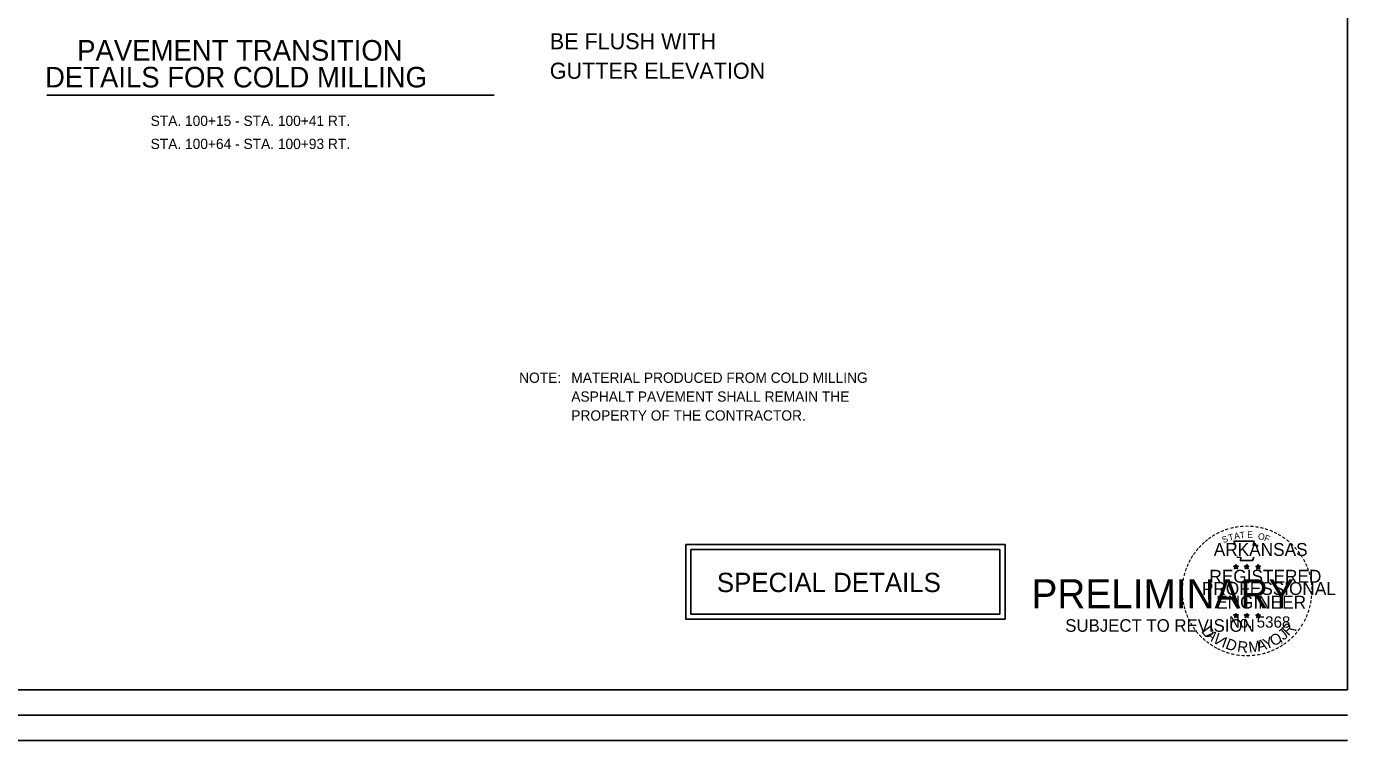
# Model space of a CAD drawing. Extents: x 1944905 to 1956777, y 763871 to 764977.
# Drawn here: x 1955751 to 1956777, y 763871 to 764425 of the extents above; entities that cross this region are included whole.
import ezdxf

# ---------------------------------------------------------------- set-up
doc = ezdxf.new("R2010")
doc.units = 0
for name, color, linetype in [('Default', 7, 'Continuous'), ('R_Border PE', 7, 'Continuous'), ('R_Dimension', 7, 'Continuous')]:
    doc.layers.add(name, color=color, linetype=linetype)

msp = doc.modelspace()

# ---------------------------------------------------------------- linework, layer by layer
at = {"layer": 'Default'}
for p, q in [((1956776.6, 763910.1), (1956776.6, 764937.3)), ((1956776.6, 763910.1), (1955195.7, 763910.1)), ((1955162.8, 763890.4), (1956776.6, 763890.4)), ((1955162.8, 763870.7), (1956776.6, 763870.7))]:
    msp.add_line(p, q, dxfattribs=at)
for points in [[(1956262.7, 764022.9), (1956510.7, 764022.9), (1956510.7, 763964.9), (1956262.7, 763964.9)], [(1956266.7, 764018.9), (1956506.7, 764018.9), (1956506.7, 763968.9), (1956266.7, 763968.9)]]:
    msp.add_lwpolyline(points, close=True, dxfattribs=at)
at = {"layer": 'R_Border PE'}
for p, q in [((1956688.2, 764006), (1956689.9, 764005.5)), ((1956688.2, 764006), (1956689.5, 764005.9)), ((1956688.2, 764006), (1956689.5, 764005.8)), ((1956688.2, 764006), (1956689.4, 764005.7)), ((1956688.2, 764006), (1956689.4, 764005.5)), ((1956688.2, 764006), (1956689.4, 764005.4)), ((1956688.2, 764006), (1956689.4, 764005.3)), ((1956689.9, 764007.3), (1956689.7, 764006)), ((1956689.9, 764007.3), (1956689.7, 764006.1)), ((1956689.9, 764005.5), (1956689.9, 764007.3)), ((1956689.9, 764007.3), (1956690.3, 764006)), ((1956689.9, 764007.3), (1956690.2, 764006)), ((1956689.9, 764007.3), (1956690.1, 764006.1)), ((1956689.9, 764007.3), (1956689.9, 764006)), ((1956691.7, 764006), (1956689.9, 764005.5)), ((1956691.7, 764006), (1956690.2, 764005.9)), ((1956691.7, 764006), (1956690.3, 764005.8)), ((1956691.7, 764006), (1956690.3, 764005.7)), ((1956691.7, 764006), (1956690.6, 764005.6)), ((1956691.7, 764006), (1956690.7, 764005.5)), ((1956691.7, 764006), (1956690.7, 764005.5)), ((1956696.5, 764006), (1956698.3, 764005.5)), ((1956696.5, 764006), (1956697.8, 764005.9)), ((1956696.5, 764006), (1956697.8, 764005.8)), ((1956696.5, 764006), (1956697.8, 764005.7)), ((1956696.5, 764006), (1956697.8, 764005.5)), ((1956696.5, 764006), (1956697.7, 764005.4)), ((1956696.5, 764006), (1956697.7, 764005.3)), ((1956698.3, 764007.3), (1956698, 764006.1)), ((1956698.3, 764007.3), (1956698.1, 764006)), ((1956698.3, 764007.3), (1956698.2, 764006)), ((1956698.3, 764005.5), (1956698.3, 764007.3)), ((1956698.3, 764007.3), (1956698.6, 764006)), ((1956698.3, 764007.3), (1956698.5, 764006)), ((1956698.3, 764007.3), (1956698.4, 764006.1)), ((1956700, 764006), (1956698.3, 764005.5)), ((1956700, 764006), (1956698.5, 764005.9)), ((1956700, 764006), (1956698.6, 764005.8)), ((1956700, 764006), (1956698.6, 764005.7)), ((1956700, 764006), (1956698.9, 764005.6)), ((1956700, 764006), (1956699, 764005.5)), ((1956700, 764006), (1956699.1, 764005.5)), ((1956705.4, 764006), (1956707.1, 764005.4)), ((1956705.4, 764006), (1956706.7, 764005.8)), ((1956705.4, 764006), (1956706.7, 764005.7)), ((1956705.4, 764006), (1956706.6, 764005.6)), ((1956705.4, 764006), (1956706.6, 764005.5)), ((1956705.4, 764006), (1956706.6, 764005.4)), ((1956705.4, 764006), (1956706.6, 764005.3)), ((1956707.1, 764007.2), (1956706.8, 764006)), ((1956707.1, 764007.2), (1956706.9, 764006)), ((1956707.1, 764007.2), (1956707, 764006)), ((1956707.1, 764005.4), (1956707.1, 764007.2)), ((1956707.1, 764007.2), (1956707.5, 764006)), ((1956707.1, 764007.2), (1956707.4, 764006)), ((1956707.1, 764007.2), (1956707.2, 764006)), ((1956708.9, 764006), (1956707.1, 764005.4)), ((1956708.9, 764006), (1956707.3, 764005.9)), ((1956708.9, 764006), (1956707.4, 764005.7)), ((1956708.9, 764006), (1956707.4, 764005.6)), ((1956708.9, 764006), (1956707.8, 764005.5)), ((1956708.9, 764006), (1956707.8, 764005.5)), ((1956708.9, 764006), (1956707.9, 764005.4)), ((1956688.9, 764004), (1956689.9, 764005.5)), ((1956688.9, 764004), (1956689.4, 764005.4)), ((1956688.9, 764004), (1956689.5, 764005.2)), ((1956688.9, 764004), (1956689.6, 764005.2)), ((1956688.9, 764004), (1956689.9, 764005.1)), ((1956688.9, 764004), (1956689.7, 764005)), ((1956688.9, 764004), (1956690, 764004.9)), ((1956691, 764004), (1956689.9, 764005.5)), ((1956691, 764004), (1956689.9, 764005.1)), ((1956691, 764004), (1956689.9, 764004.9)), ((1956691, 764004), (1956690.1, 764005)), ((1956691, 764004), (1956690.3, 764005.4)), ((1956691, 764004), (1956690.3, 764005.2)), ((1956691, 764004), (1956690.4, 764005.4)), ((1956697.2, 764004), (1956698.3, 764005.5)), ((1956697.2, 764004), (1956697.8, 764005.4)), ((1956697.2, 764004), (1956697.8, 764005.2)), ((1956697.2, 764004), (1956697.9, 764005.2)), ((1956697.2, 764004), (1956698.3, 764005.1)), ((1956697.2, 764004), (1956698.1, 764005)), ((1956697.2, 764004), (1956698.3, 764004.9)), ((1956699.4, 764004), (1956698.3, 764005.5)), ((1956699.4, 764004), (1956698.3, 764005.1)), ((1956699.4, 764004), (1956698.3, 764004.9)), ((1956699.4, 764004), (1956698.5, 764005)), ((1956699.4, 764004), (1956698.6, 764005.2)), ((1956699.4, 764004), (1956698.7, 764005.4)), ((1956699.4, 764004), (1956698.8, 764005.4)), ((1956706.1, 764003.9), (1956707.1, 764005.4)), ((1956706.1, 764003.9), (1956706.6, 764005.3)), ((1956706.1, 764003.9), (1956706.7, 764005.1)), ((1956706.1, 764003.9), (1956706.8, 764005.1)), ((1956706.1, 764003.9), (1956706.9, 764005)), ((1956706.1, 764003.9), (1956707.1, 764005)), ((1956706.1, 764003.9), (1956707.2, 764004.9)), ((1956708.2, 764003.9), (1956707.1, 764005.4)), ((1956708.2, 764003.9), (1956707.1, 764005)), ((1956708.2, 764003.9), (1956707.1, 764004.9)), ((1956708.2, 764003.9), (1956707.3, 764005)), ((1956708.2, 764003.9), (1956707.5, 764005.4)), ((1956708.2, 764003.9), (1956707.5, 764005.2)), ((1956708.2, 764003.9), (1956707.6, 764005.4)), ((1956688.2, 763968.2), (1956689.9, 763967.6)), ((1956688.2, 763968.2), (1956689.5, 763968)), ((1956688.2, 763968.2), (1956689.5, 763967.9)), ((1956688.2, 763968.2), (1956689.4, 763967.8)), ((1956688.2, 763968.2), (1956689.4, 763967.7)), ((1956688.2, 763968.2), (1956689.4, 763967.6)), ((1956688.2, 763968.2), (1956689.4, 763967.4)), ((1956688.9, 763966.1), (1956689.9, 763967.6)), ((1956688.9, 763966.1), (1956689.4, 763967.5)), ((1956688.9, 763966.1), (1956689.5, 763967.3)), ((1956688.9, 763966.1), (1956689.6, 763967.3)), ((1956688.9, 763966.1), (1956689.7, 763967.2)), ((1956688.9, 763966.1), (1956689.9, 763967.2)), ((1956688.9, 763966.1), (1956690, 763967.1)), ((1956689.9, 763969.4), (1956689.6, 763968.2)), ((1956689.9, 763969.4), (1956689.7, 763968.2)), ((1956689.9, 763969.4), (1956689.8, 763968.2)), ((1956689.9, 763967.6), (1956689.9, 763969.4)), ((1956689.9, 763969.4), (1956690.3, 763968.2)), ((1956689.9, 763969.4), (1956690.2, 763968.2)), ((1956689.9, 763969.4), (1956690, 763968.2)), ((1956691.7, 763968.2), (1956689.9, 763967.6)), ((1956691, 763966.1), (1956689.9, 763967.6)), ((1956691, 763966.1), (1956689.9, 763967.2)), ((1956691, 763966.1), (1956689.9, 763967.1)), ((1956691.7, 763968.2), (1956690.1, 763968.1)), ((1956691, 763966.1), (1956690.1, 763967.2)), ((1956691.7, 763968.2), (1956690.2, 763967.9)), ((1956691.7, 763968.2), (1956690.2, 763967.8)), ((1956691, 763966.1), (1956690.3, 763967.6)), ((1956691, 763966.1), (1956690.3, 763967.3)), ((1956691, 763966.1), (1956690.4, 763967.6)), ((1956691.7, 763968.2), (1956690.6, 763967.7)), ((1956691.7, 763968.2), (1956690.6, 763967.7)), ((1956691.7, 763968.2), (1956690.7, 763967.6)), ((1956696.5, 763968.2), (1956698.3, 763967.6)), ((1956696.5, 763968.2), (1956697.8, 763968)), ((1956696.5, 763968.2), (1956697.8, 763967.9)), ((1956696.5, 763968.2), (1956697.8, 763967.8)), ((1956696.5, 763968.2), (1956697.7, 763967.7)), ((1956696.5, 763968.2), (1956697.7, 763967.6)), ((1956696.5, 763968.2), (1956697.7, 763967.4)), ((1956697.2, 763966.1), (1956698.3, 763967.6)), ((1956697.2, 763966.1), (1956697.8, 763967.5)), ((1956697.2, 763966.1), (1956697.8, 763967.3)), ((1956697.2, 763966.1), (1956697.9, 763967.3)), ((1956697.2, 763966.1), (1956698.1, 763967.2)), ((1956697.2, 763966.1), (1956698.3, 763967.2)), ((1956697.2, 763966.1), (1956698.3, 763967.1)), ((1956698.3, 763969.4), (1956698, 763968.2)), ((1956698.3, 763969.4), (1956698.1, 763968.2)), ((1956698.3, 763969.4), (1956698.2, 763968.2)), ((1956698.3, 763967.6), (1956698.3, 763969.4)), ((1956698.3, 763969.4), (1956698.6, 763968.2)), ((1956698.3, 763969.4), (1956698.5, 763968.2)), ((1956698.3, 763969.4), (1956698.4, 763968.2)), ((1956700, 763968.2), (1956698.3, 763967.6)), ((1956699.3, 763966.1), (1956698.3, 763967.6)), ((1956699.3, 763966.1), (1956698.3, 763967.2)), ((1956699.3, 763966.1), (1956698.3, 763967.1)), ((1956700, 763968.2), (1956698.5, 763968.1)), ((1956699.3, 763966.1), (1956698.5, 763967.2)), ((1956700, 763968.2), (1956698.6, 763967.9)), ((1956700, 763968.2), (1956698.6, 763967.8)), ((1956699.3, 763966.1), (1956698.6, 763967.3)), ((1956699.3, 763966.1), (1956698.7, 763967.6)), ((1956699.3, 763966.1), (1956698.8, 763967.6)), ((1956700, 763968.2), (1956698.9, 763967.7)), ((1956700, 763968.2), (1956699, 763967.7)), ((1956700, 763968.2), (1956699.1, 763967.6)), ((1956705.4, 763968.1), (1956707.1, 763967.5)), ((1956705.4, 763968.1), (1956706.6, 763968)), ((1956705.4, 763968.1), (1956706.6, 763967.9)), ((1956705.4, 763968.1), (1956706.6, 763967.8)), ((1956705.4, 763968.1), (1956706.6, 763967.6)), ((1956705.4, 763968.1), (1956706.5, 763967.5)), ((1956705.4, 763968.1), (1956706.5, 763967.4)), ((1956706, 763966.1), (1956707.1, 763967.5)), ((1956706, 763966.1), (1956706.6, 763967.4)), ((1956706, 763966.1), (1956706.7, 763967.3)), ((1956706, 763966.1), (1956706.8, 763967.2)), ((1956706, 763966.1), (1956706.9, 763967.1)), ((1956706, 763966.1), (1956707.1, 763967.1)), ((1956706, 763966.1), (1956707.1, 763967)), ((1956707.1, 763969.4), (1956706.8, 763968.1)), ((1956707.1, 763969.4), (1956706.9, 763968.1)), ((1956707.1, 763969.4), (1956707, 763968.1)), ((1956707.1, 763967.5), (1956707.1, 763969.4)), ((1956707.1, 763969.4), (1956707.4, 763968.1)), ((1956707.1, 763969.4), (1956707.4, 763968.1)), ((1956707.1, 763969.4), (1956707.2, 763968.1)), ((1956708.8, 763968.1), (1956707.1, 763967.5)), ((1956708.2, 763966.1), (1956707.1, 763967.5)), ((1956708.2, 763966.1), (1956707.1, 763967.1)), ((1956708.2, 763966.1), (1956707.1, 763967)), ((1956708.8, 763968.1), (1956707.3, 763968)), ((1956708.2, 763966.1), (1956707.3, 763967.1)), ((1956708.8, 763968.1), (1956707.4, 763967.9)), ((1956708.8, 763968.1), (1956707.4, 763967.8)), ((1956708.2, 763966.1), (1956707.5, 763967.5)), ((1956708.2, 763966.1), (1956707.5, 763967.3)), ((1956708.2, 763966.1), (1956707.6, 763967.5)), ((1956708.8, 763968.1), (1956707.7, 763967.6)), ((1956708.8, 763968.1), (1956707.8, 763967.6)), ((1956708.8, 763968.1), (1956707.9, 763967.5))]:
    msp.add_line(p, q, dxfattribs=at)
for points in [[(1956688.4, 764025.4), (1956689.8, 764021.3)], [(1956706, 764020.8), (1956706.7, 764022.2), (1956703.2, 764022.1), (1956704, 764025.4), (1956688.4, 764025.4)], [(1956689.9, 764007.3), (1956691, 764004), (1956688.2, 764006), (1956691.7, 764006), (1956688.9, 764004), (1956689.9, 764007.3)], [(1956690.9, 764013.3), (1956690.9, 764012.9), (1956693.7, 764012.8), (1956693.4, 764010.4), (1956702.8, 764010.4), (1956703.8, 764013.1)], [(1956698.3, 764007.3), (1956699.4, 764004), (1956696.5, 764006), (1956700, 764006), (1956697.2, 764004), (1956698.3, 764007.3)], [(1956707.1, 764007.2), (1956708.2, 764003.9), (1956705.4, 764006), (1956708.9, 764006), (1956706.1, 764003.9), (1956707.1, 764007.2)], [(1956689.9, 763969.4), (1956691, 763966.1), (1956688.2, 763968.2), (1956691.7, 763968.2), (1956688.9, 763966.1), (1956689.9, 763969.4)], [(1956698.3, 763969.4), (1956699.3, 763966.1), (1956696.5, 763968.2), (1956700, 763968.2), (1956697.2, 763966.1), (1956698.3, 763969.4)], [(1956707.1, 763969.4), (1956708.2, 763966.1), (1956705.4, 763968.1), (1956708.8, 763968.1), (1956706, 763966.1), (1956707.1, 763969.4)]]:
    msp.add_lwpolyline(points, dxfattribs=at)
for centre, radius in [((1956689.9, 764005.5), 0.861), ((1956689.9, 764005.5), 0.78), ((1956689.9, 764005.5), 0.723), ((1956689.9, 764005.5), 0.664), ((1956689.9, 764005.5), 0.579), ((1956689.9, 764005.5), 0.537), ((1956698.3, 764005.5), 0.861), ((1956698.3, 764005.5), 0.78), ((1956698.3, 764005.5), 0.723), ((1956698.3, 764005.5), 0.664), ((1956698.3, 764005.5), 0.579), ((1956698.3, 764005.5), 0.537), ((1956707.1, 764005.4), 0.861), ((1956707.1, 764005.4), 0.78), ((1956707.1, 764005.4), 0.723), ((1956707.1, 764005.4), 0.664), ((1956707.1, 764005.4), 0.579), ((1956689.9, 764005.5), 0.495), ((1956689.9, 764005.5), 0.426), ((1956689.9, 764005.5), 0.374), ((1956689.9, 764005.5), 0.311), ((1956689.9, 764005.5), 0.248), ((1956689.9, 764005.5), 0.185), ((1956689.9, 764005.5), 0.148), ((1956689.9, 764005.5), 0.0721), ((1956698.3, 764005.5), 0.495), ((1956698.3, 764005.5), 0.426), ((1956698.3, 764005.5), 0.374), ((1956698.3, 764005.5), 0.311), ((1956698.3, 764005.5), 0.248), ((1956698.3, 764005.5), 0.185), ((1956698.3, 764005.5), 0.148), ((1956698.3, 764005.5), 0.0721), ((1956707.1, 764005.4), 0.537), ((1956707.1, 764005.4), 0.495), ((1956707.1, 764005.4), 0.426), ((1956707.1, 764005.4), 0.374), ((1956707.1, 764005.4), 0.311), ((1956707.1, 764005.4), 0.248), ((1956707.1, 764005.4), 0.185), ((1956707.1, 764005.4), 0.148), ((1956707.1, 764005.4), 0.0721), ((1956689.9, 763967.6), 0.861), ((1956689.9, 763967.6), 0.78), ((1956689.9, 763967.6), 0.723), ((1956689.9, 763967.6), 0.664), ((1956689.9, 763967.6), 0.579), ((1956689.9, 763967.6), 0.537), ((1956689.9, 763967.6), 0.495), ((1956689.9, 763967.6), 0.426), ((1956689.9, 763967.6), 0.374), ((1956689.9, 763967.6), 0.311), ((1956689.9, 763967.6), 0.248), ((1956689.9, 763967.6), 0.185), ((1956689.9, 763967.6), 0.148), ((1956689.9, 763967.6), 0.0721), ((1956698.3, 763967.6), 0.861), ((1956698.3, 763967.6), 0.78), ((1956698.3, 763967.6), 0.723), ((1956698.3, 763967.6), 0.664), ((1956698.3, 763967.6), 0.579), ((1956698.3, 763967.6), 0.537), ((1956698.3, 763967.6), 0.495), ((1956698.3, 763967.6), 0.426), ((1956698.3, 763967.6), 0.374), ((1956698.3, 763967.6), 0.311), ((1956698.3, 763967.6), 0.248), ((1956698.3, 763967.6), 0.185), ((1956698.3, 763967.6), 0.148), ((1956698.3, 763967.6), 0.0721), ((1956707.1, 763967.6), 0.861), ((1956707.1, 763967.6), 0.78), ((1956707.1, 763967.6), 0.723), ((1956707.1, 763967.6), 0.664), ((1956707.1, 763967.6), 0.579), ((1956707.1, 763967.6), 0.495), ((1956707.1, 763967.6), 0.537), ((1956707.1, 763967.6), 0.426), ((1956707.1, 763967.6), 0.374), ((1956707.1, 763967.6), 0.311), ((1956707.1, 763967.6), 0.248), ((1956707.1, 763967.6), 0.185), ((1956707.1, 763967.6), 0.148), ((1956707.1, 763967.6), 0.0721)]:
    msp.add_circle(centre, radius, dxfattribs=at)
at = {"layer": 'R_Dimension'}
msp.add_line((1955766.8, 764371.7), (1956113.9, 764371.7), dxfattribs=at)

# ---------------------------------------------------------------- texts
at = {"layer": 'Default'}
for s, height, p in [('SPECIAL DETAILS', 15, (1956286.9, 763985.9)), ('PRELIMINARY', 22.5, (1956531.2, 763973.4)), ('        SUBJECT TO REVISION', 9.75, (1956528.4, 763955.1))]:
    msp.add_text(s, height=height, dxfattribs=at).set_placement(p)
at = {"layer": 'R_Border PE'}
for s, height, rotation, p in [('-', 8, 10.2193, (1956689.3, 764033.1)), ('-', 8, 5.8968, (1956692.9, 764033.6)), ('-', 8, 0.1862, (1956696.8, 764034)), ('-', 8, 357.743, (1956700.4, 764033.9)), ('-', 8, 352.1617, (1956704.1, 764033.6)), ('-', 8, 38.9507, (1956667.6, 764022.4)), ('-', 8, 36.2317, (1956669.9, 764024.3)), ('-', 8, 34.0636, (1956672.8, 764026.3)), ('-', 8, 28.7918, (1956675.8, 764028.1)), ('-', 8, 24.3072, (1956679, 764029.7)), ('S', 5, 21.594, (1956680.2, 764023.8)), ('-', 8, 19.1761, (1956682.1, 764031.1)), ('T', 5, 16.4036, (1956684.8, 764025.5)), ('-', 8, 13.6301, (1956685.9, 764032.3)), ('A', 5, 11.2132, (1956688.9, 764026.7)), ('T', 5, 6.0228, (1956693.1, 764027.5)), ('E', 5, 0.8323, (1956698.7, 764028.1)), ('O', 5, 350.4515, (1956706.7, 764027)), ('-', 8, 347.2049, (1956707.7, 764033.1)), ('F', 5, 340.0707, (1956711.4, 764025.9)), ('-', 8, 342.3362, (1956710.9, 764032.3)), ('-', 8, 337.8551, (1956714.6, 764031.2)), ('-', 8, 334.1211, (1956717.7, 764029.8)), ('-', 8, 329.6409, (1956720.6, 764028.4)), ('-', 8, 325.8627, (1956723.8, 764026.6)), ('-', 8, 320.5297, (1956726.9, 764024.5)), ('-', 8, 54.2325, (1956659.1, 764012.7)), ('-', 8, 50.6142, (1956661.1, 764015.5)), ('-', 8, 48.4231, (1956663.2, 764017.9)), ('-', 8, 42.9622, (1956665.4, 764020.3)), ('-', 8, 315.5786, (1956729.9, 764022)), ('-', 8, 309.8797, (1956732.7, 764019.3)), ('-', 8, 306.6522, (1956735.4, 764016.3)), ('-', 8, 67.7743, (1956654.6, 764003.9)), ('-', 8, 62.8713, (1956655.9, 764007)), ('-', 8, 58.0706, (1956657.4, 764010)), ('-', 7, 303.6753, (1956737.8, 764013.4)), ('-', 8, 299.6684, (1956739.4, 764010.4)), ('-', 8, 294.6628, (1956741, 764007.3)), ('-', 8, 81.2013, (1956651.8, 763993.6)), ('-', 8, 75.461, (1956652.5, 763997.2)), ('-', 8, 72.3945, (1956653.5, 764000.8)), ('-', 8, 290.5728, (1956742.3, 764004.4)), ('-', 8, 285.1233, (1956743.5, 764001.5)), ('-', 8, 280.5493, (1956744.5, 763997.8)), ('-', 8, 89.0622, (1956651.3, 763986.7)), ('-', 8, 94.1959, (1956651.5, 763983)), ('-', 8, 85.1863, (1956651.5, 763990.2)), ('-', 8, 276.5962, (1956745.3, 763994)), ('-', 8, 274.3301, (1956745.6, 763990.4)), ('-', 8, 269.9407, (1956745.7, 763987.2)), ('-', 8, 98.9479, (1956651.9, 763979.7)), ('-', 8, 101.7149, (1956652.6, 763976)), ('-', 8, 105.4578, (1956653.4, 763973.1)), ('-', 8, 255.7626, (1956744.7, 763977.2)), ('-', 8, 260.9953, (1956745.3, 763980.6)), ('-', 8, 263.5172, (1956745.6, 763983.9)), ('-', 8, 109.0874, (1956654.4, 763969.9)), ('-', 8, 114.0643, (1956655.7, 763966.9)), ('-', 8, 115.7289, (1956657.2, 763963.8)), ('-', 8, 244.6197, (1956741.4, 763967.1)), ('-', 8, 247.8887, (1956742.7, 763970.3)), ('-', 8, 252.8681, (1956743.8, 763973.6)), ('-', 8, 120.4471, (1956659, 763960.9)), ('-', 8, 125.8934, (1956661, 763958.1)), ('-', 8, 130.7181, (1956663.3, 763955.3)), ('D', 8.47, 308.0267, (1956662.6, 763955.4)), ('A', 7.7, 314.1683, (1956666.3, 763952)), ('J', 8.47, 40.1506, (1956726.9, 763948.1)), ('R', 8.47, 46.2922, (1956730.7, 763951.4)), ('-', 8, 231.2538, (1956735.3, 763957.3)), ('-', 8, 233.8452, (1956737.4, 763960.1)), ('-', 8, 239.0712, (1956739.4, 763963.4)), ('-', 8, 134.2238, (1956665.9, 763952.6)), ('-', 8, 138.9338, (1956668.6, 763950.3)), ('-', 8, 144.6463, (1956671.3, 763948.3)), ('-', 8, 148.0898, (1956674.1, 763946.4)), ('V', 8.47, 322.0751, (1956671, 763947.9)), ('ID', 8.47, 339.2447, (1956678.2, 763943.5)), ('R', 8.47, 351.4846, (1956690.5, 763939.9)), ('M', 8.47, 7.3842, (1956700.2, 763938.8)), ('A', 8.47, 15.0444, (1956707.2, 763939.7)), ('Y', 8.47, 21.7259, (1956713, 763941.1)), ('O', 8.47, 27.8675, (1956718.9, 763943.5)), ('-', 8, 212.2491, (1956724.9, 763947.6)), (',', 8.45, 13.6684, (1956723.8, 763946.7)), ('-', 8, 215.7363, (1956727.5, 763949.5)), ('-', 8, 221.0851, (1956730.3, 763951.9)), ('-', 8, 225.7653, (1956732.9, 763954.5)), ('-', 8, 151.5704, (1956677, 763944.8)), ('-', 8, 154.6002, (1956679.6, 763943.6)), ('-', 8, 158.5612, (1956682.8, 763942.3)), ('-', 8, 162.7983, (1956686.2, 763941.2)), ('-', 8, 167.5555, (1956689.8, 763940.4)), ('-', 8, 173.1155, (1956693.6, 763939.8)), ('-', 8, 176.5183, (1956697.4, 763939.6)), ('.', 7.7, 351.0179, (1956696.3, 763939)), ('-', 8, 181.5918, (1956701.1, 763939.7)), ('-', 8, 185.8167, (1956705.1, 763940.1)), ('-', 8, 191.2858, (1956708.8, 763940.7)), ('-', 8, 195.4743, (1956712.5, 763941.7)), ('-', 8, 200.7184, (1956715.8, 763942.9)), ('-', 8, 204.2516, (1956718.9, 763944.3)), ('-', 8, 207.3568, (1956722.1, 763945.9))]:
    msp.add_text(s, height=height, rotation=rotation, dxfattribs=at).set_placement(p)
for s, height, p in [('ARKANSAS', 10, (1956672.7, 764014)), ('REGISTERED', 10, (1956669.3, 763993.2)), ('PROFESSIONAL', 10, (1956663.5, 763983.7)), ('ENGINEER', 10, (1956674.5, 763973.1)), ('No. 5368', 8.78, (1956684.5, 763958.3)), ('.', 8.45, (1956734.7, 763955.8))]:
    msp.add_text(s, height=height, dxfattribs=at).set_placement(p)
at = {"layer": 'R_Dimension'}
for s, height, p in [('BE FLUSH WITH', 12.504, (1956157.2, 764407.2)), ('PAVEMENT TRANSITION', 15.963, (1955790.3, 764398.4)), ('GUTTER ELEVATION', 12.504, (1956157.2, 764384.3)), ('DETAILS FOR COLD MILLING', 15.963, (1955765.3, 764377.6)), ('STA. 100+15 - STA. 100+41 RT.', 7.982, (1955847.3, 764347.7)), ('STA. 100+64 - STA. 100+93 RT.', 7.982, (1955847.3, 764329.8)), ('NOTE: ', 7.98, (1956133.4, 764148.3)), ('MATERIAL PRODUCED FROM COLD MILLING', 7.982, (1956173.9, 764148.3)), ('ASPHALT PAVEMENT SHALL REMAIN THE', 7.982, (1956173.9, 764133.7)), ('PROPERTY OF THE CONTRACTOR.', 7.982, (1956173.9, 764119))]:
    msp.add_text(s, height=height, dxfattribs=at).set_placement(p)

doc.saveas('drawing.dxf')
